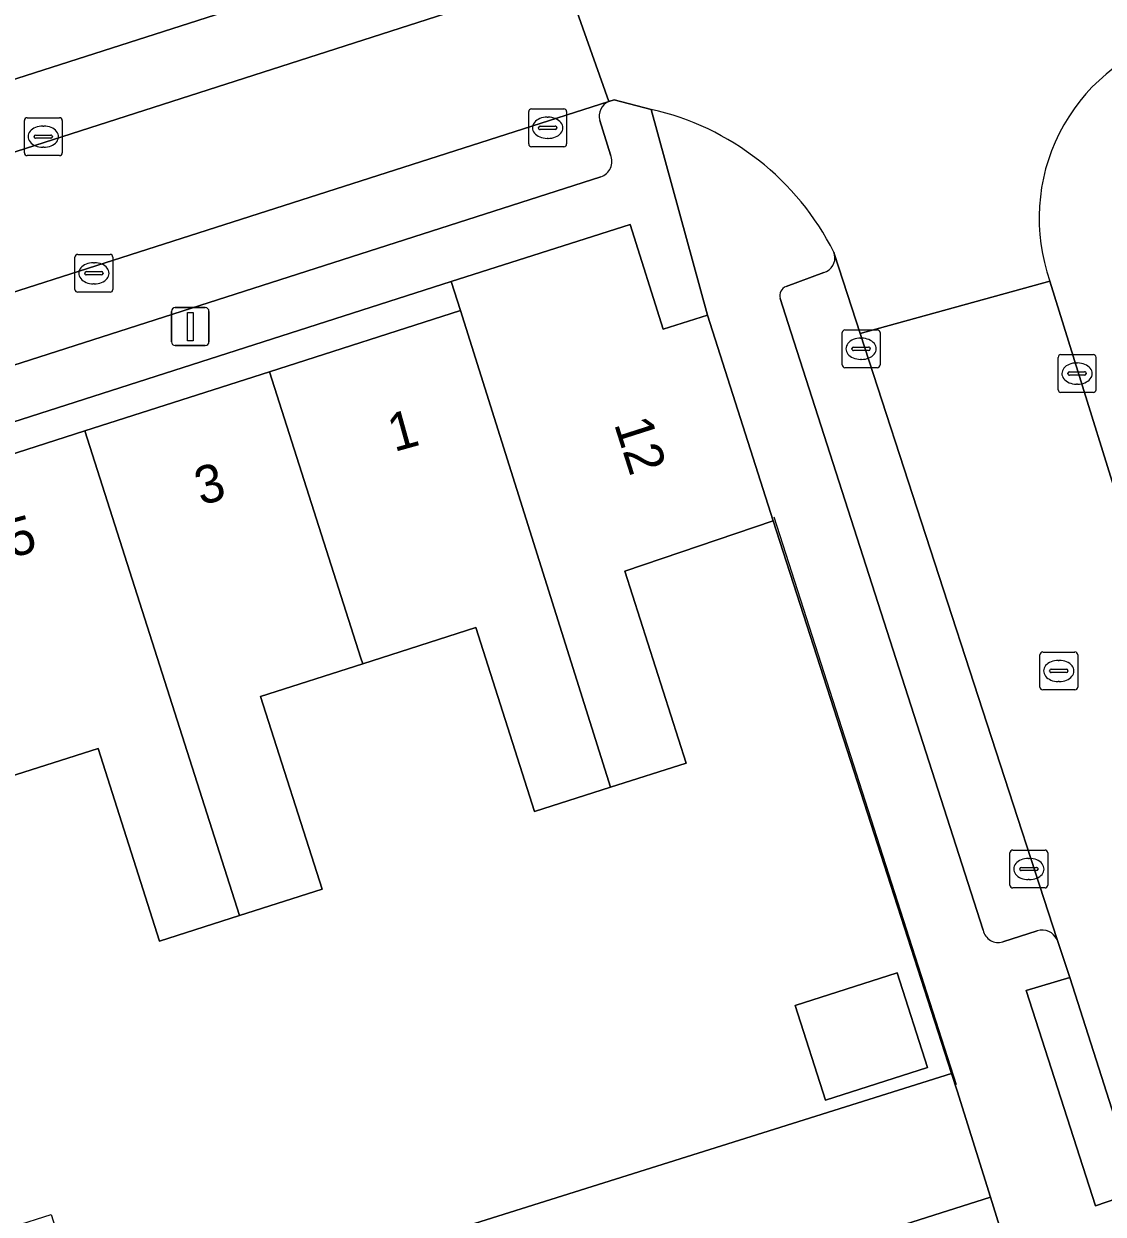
# Model space of a CAD drawing. Extents: x 159716 to 160783, y 383290 to 384031.
# Drawn here: x 160111.85 to 160140.37, y 383651.79 to 383683.23 of the extents above; entities that cross this region are included whole.
import ezdxf

# ---------------------------------------------------------------- set-up
doc = ezdxf.new("R2010")
doc.units = 0
for name, color, linetype in [('IMGEO_Erf', 7, 'Continuous'), ('IMGEO_Kolk', 7, 'Continuous'), ('IMGEO_Lichtmast', 7, 'Continuous'), ('IMGEO_Muur', 7, 'Continuous'), ('IMGEO_Pand', 7, 'Continuous'), ('IMGEO_Pand_nummerreeks', 7, 'Continuous'), ('IMGEO_Parkeervlak_open', 7, 'Continuous'), ('IMGEO_Rijbaan_lokaal_open', 7, 'Continuous'), ('IMGEO_Rioolput', 7, 'Continuous'), ('IMGEO_Voetpad_open', 7, 'Continuous')]:
    doc.layers.add(name, color=color, linetype=linetype)

msp = doc.modelspace()

# ---------------------------------------------------------------- linework, layer by layer
at = {"layer": 'IMGEO_Erf'}
for points in [[(160118.342, 383674.043), (160123.386, 383675.66), (160123.144, 383676.422), (160103.512, 383670.129), (160103.756, 383669.367), (160108.583, 383670.914), (160113.462, 383672.478)], [(160133.029, 383654.803), (160132.229, 383657.304), (160134.927, 383658.167), (160135.726, 383655.666)], [(160137.393, 383652.245), (160134.204, 383651.225), (160134.948, 383648.933), (160138.096, 383649.97)]]:
    msp.add_lwpolyline(points, close=True, dxfattribs=at)
msp.add_lwpolyline([(160109.579, 383650.836), (160112.572, 383651.783), (160113.511, 383648.814), (160115.357, 383649.398), (160115.5, 383648.947), (160136.361, 383655.511), (160131.65, 383670.104), (160127.73, 383668.779), (160129.351, 383663.706), (160127.35, 383663.067), (160125.347, 383662.428), (160123.796, 383667.287), (160120.805, 383666.331), (160118.108, 383665.469), (160119.734, 383660.377), (160117.551, 383659.679), (160115.439, 383659.005), (160113.814, 383664.092), (160111.044, 383663.207)], dxfattribs=at)
at = {"layer": 'IMGEO_Kolk'}
for p, q in [((160125.266, 383680.986), (160126.118, 383680.986)), ((160111.866, 383679.826), (160111.866, 383680.678)), ((160111.941, 383680.752), (160112.793, 383680.752)), ((160112.867, 383680.678), (160112.867, 383679.826)), ((160125.191, 383680.06), (160125.191, 383680.912)), ((160125.679, 383680.766), (160125.704, 383680.766)), ((160126.192, 383680.912), (160126.192, 383680.06)), ((160112.354, 383680.532), (160112.379, 383680.532)), ((160125.45, 383680.48), (160125.45, 383680.492)), ((160125.888, 383680.443), (160125.49, 383680.443)), ((160125.493, 383680.529), (160125.891, 383680.529)), ((160125.934, 383680.492), (160125.934, 383680.48)), ((160112.125, 383680.246), (160112.125, 383680.258)), ((160112.563, 383680.209), (160112.165, 383680.209)), ((160112.168, 383680.295), (160112.566, 383680.295)), ((160112.609, 383680.258), (160112.609, 383680.246)), ((160125.702, 383680.206), (160125.677, 383680.206)), ((160112.793, 383679.752), (160111.941, 383679.752)), ((160112.377, 383679.972), (160112.352, 383679.972)), ((160126.118, 383679.986), (160125.266, 383679.986)), ((160113.203, 383676.217), (160113.203, 383677.069)), ((160113.278, 383677.143), (160114.13, 383677.143)), ((160113.691, 383676.923), (160113.716, 383676.923)), ((160114.204, 383677.069), (160114.204, 383676.217)), ((160113.462, 383676.637), (160113.462, 383676.649)), ((160113.9, 383676.6), (160113.502, 383676.6)), ((160113.505, 383676.686), (160113.903, 383676.686)), ((160113.946, 383676.649), (160113.946, 383676.637)), ((160113.714, 383676.363), (160113.689, 383676.363)), ((160114.13, 383676.143), (160113.278, 383676.143)), ((160133.472, 383674.223), (160133.472, 383675.075)), ((160133.547, 383675.149), (160134.399, 383675.149)), ((160134.473, 383675.075), (160134.473, 383674.223)), ((160133.731, 383674.643), (160133.731, 383674.655)), ((160133.774, 383674.692), (160134.172, 383674.692)), ((160133.96, 383674.929), (160133.985, 383674.929)), ((160134.215, 383674.655), (160134.215, 383674.643)), ((160134.169, 383674.606), (160133.771, 383674.606)), ((160133.983, 383674.369), (160133.958, 383674.369)), ((160139.177, 383673.569), (160139.177, 383674.421)), ((160139.252, 383674.495), (160140.104, 383674.495)), ((160140.178, 383674.421), (160140.178, 383673.569)), ((160134.399, 383674.149), (160133.547, 383674.149)), ((160139.479, 383674.038), (160139.877, 383674.038)), ((160139.665, 383674.275), (160139.69, 383674.275)), ((160139.436, 383673.989), (160139.436, 383674.001)), ((160139.874, 383673.952), (160139.476, 383673.952)), ((160139.688, 383673.715), (160139.663, 383673.715)), ((160139.92, 383674.001), (160139.92, 383673.989)), ((160140.104, 383673.495), (160139.252, 383673.495)), ((160137.904, 383660.482), (160137.904, 383661.334)), ((160137.979, 383661.408), (160138.831, 383661.408)), ((160138.392, 383661.188), (160138.417, 383661.188)), ((160138.905, 383661.334), (160138.905, 383660.482)), ((160138.163, 383660.902), (160138.163, 383660.914)), ((160138.601, 383660.865), (160138.203, 383660.865)), ((160138.206, 383660.951), (160138.604, 383660.951)), ((160138.647, 383660.914), (160138.647, 383660.902)), ((160138.415, 383660.628), (160138.39, 383660.628)), ((160138.831, 383660.408), (160137.979, 383660.408))]:
    msp.add_line(p, q, dxfattribs=at)
for points in [[(160125.266, 383680.986), (160126.118, 383680.986)], [(160111.866, 383679.826), (160111.866, 383680.678)], [(160111.941, 383680.752), (160112.793, 383680.752)], [(160112.867, 383680.678), (160112.867, 383679.826)], [(160125.191, 383680.06), (160125.191, 383680.912)], [(160126.192, 383680.912), (160126.192, 383680.06)], [(160112.793, 383679.752), (160111.941, 383679.752)], [(160126.118, 383679.986), (160125.266, 383679.986)], [(160113.203, 383676.217), (160113.203, 383677.069)], [(160113.278, 383677.143), (160114.13, 383677.143)], [(160114.204, 383677.069), (160114.204, 383676.217)], [(160114.13, 383676.143), (160113.278, 383676.143)], [(160133.472, 383674.223), (160133.472, 383675.075)], [(160133.547, 383675.149), (160134.399, 383675.149)], [(160134.473, 383675.075), (160134.473, 383674.223)], [(160139.177, 383673.569), (160139.177, 383674.421)], [(160139.252, 383674.495), (160140.104, 383674.495)], [(160140.178, 383674.421), (160140.178, 383673.569)], [(160134.399, 383674.149), (160133.547, 383674.149)], [(160140.104, 383673.495), (160139.252, 383673.495)], [(160137.904, 383660.482), (160137.904, 383661.334)], [(160137.979, 383661.408), (160138.831, 383661.408)], [(160138.905, 383661.334), (160138.905, 383660.482)], [(160138.831, 383660.408), (160137.979, 383660.408)]]:
    msp.add_lwpolyline(points, dxfattribs=at)
for centre, radius, start, end in [((160125.268, 383680.91), 0.0765, 91.552, 178.448), ((160125.268, 383680.91), 0.0765, 91.552, 178.448), ((160126.116, 383680.91), 0.0765, 1.552, 88.448), ((160126.116, 383680.91), 0.0765, 1.552, 88.448), ((160111.943, 383680.676), 0.0765, 91.552, 178.448), ((160111.943, 383680.676), 0.0765, 91.552, 178.448), ((160112.791, 383680.676), 0.0765, 1.552, 88.448), ((160112.791, 383680.676), 0.0765, 1.552, 88.448), ((160125.49, 383680.489), 0.0403, 85.8775, 175.7526), ((160125.487, 383680.479), 0.0366, 178.938, 274.7102), ((160125.891, 383680.486), 0.043, 264.8664, 352.4533), ((160125.895, 383680.491), 0.0386, 1.7309, 96.639), ((160112.165, 383680.255), 0.0403, 85.8775, 175.7526), ((160112.162, 383680.245), 0.0366, 178.938, 274.7102), ((160112.566, 383680.252), 0.043, 264.8664, 352.4533), ((160112.57, 383680.257), 0.0386, 1.7309, 96.639), ((160125.268, 383680.062), 0.0765, 181.552, 268.448), ((160125.268, 383680.062), 0.0765, 181.552, 268.448), ((160126.116, 383680.062), 0.0765, 271.552, 358.448), ((160126.116, 383680.062), 0.0765, 271.552, 358.448), ((160111.943, 383679.828), 0.0765, 181.552, 268.448), ((160111.943, 383679.828), 0.0765, 181.552, 268.448), ((160112.791, 383679.828), 0.0765, 271.552, 358.448), ((160112.791, 383679.828), 0.0765, 271.552, 358.448), ((160113.28, 383677.067), 0.0765, 91.552, 178.448), ((160113.28, 383677.067), 0.0765, 91.552, 178.448), ((160114.128, 383677.067), 0.0765, 1.552, 88.448), ((160114.128, 383677.067), 0.0765, 1.552, 88.448), ((160113.502, 383676.646), 0.0403, 85.8775, 175.7526), ((160113.499, 383676.636), 0.0366, 178.938, 274.7102), ((160113.903, 383676.643), 0.043, 264.8664, 352.4533), ((160113.907, 383676.648), 0.0386, 1.7309, 96.639), ((160113.28, 383676.219), 0.0765, 181.552, 268.448), ((160113.28, 383676.219), 0.0765, 181.552, 268.448), ((160114.128, 383676.219), 0.0765, 271.552, 358.448), ((160114.128, 383676.219), 0.0765, 271.552, 358.448), ((160133.549, 383675.073), 0.0765, 91.552, 178.448), ((160133.549, 383675.073), 0.0765, 91.552, 178.448), ((160134.397, 383675.073), 0.0765, 1.552, 88.448), ((160134.397, 383675.073), 0.0765, 1.552, 88.448), ((160133.771, 383674.652), 0.0403, 85.8775, 175.7526), ((160134.176, 383674.654), 0.0386, 1.7309, 96.639), ((160133.768, 383674.642), 0.0366, 178.938, 274.7102), ((160134.172, 383674.649), 0.043, 264.8664, 352.4533), ((160139.254, 383674.419), 0.0765, 91.552, 178.448), ((160139.254, 383674.419), 0.0765, 91.552, 178.448), ((160140.102, 383674.419), 0.0765, 1.552, 88.448), ((160140.102, 383674.419), 0.0765, 1.552, 88.448), ((160133.549, 383674.225), 0.0765, 181.552, 268.448), ((160133.549, 383674.225), 0.0765, 181.552, 268.448), ((160134.397, 383674.225), 0.0765, 271.552, 358.448), ((160134.397, 383674.225), 0.0765, 271.552, 358.448), ((160139.476, 383673.998), 0.0403, 85.8775, 175.7526), ((160139.881, 383674), 0.0386, 1.7309, 96.639), ((160139.473, 383673.988), 0.0366, 178.938, 274.7102), ((160139.877, 383673.995), 0.043, 264.8664, 352.4533), ((160139.254, 383673.571), 0.0765, 181.552, 268.448), ((160139.254, 383673.571), 0.0765, 181.552, 268.448), ((160140.102, 383673.571), 0.0765, 271.552, 358.448), ((160140.102, 383673.571), 0.0765, 271.552, 358.448), ((160137.981, 383661.332), 0.0765, 91.552, 178.448), ((160137.981, 383661.332), 0.0765, 91.552, 178.448), ((160138.829, 383661.332), 0.0765, 1.552, 88.448), ((160138.829, 383661.332), 0.0765, 1.552, 88.448), ((160138.203, 383660.911), 0.0403, 85.8775, 175.7526), ((160138.2, 383660.901), 0.0366, 178.938, 274.7102), ((160138.604, 383660.908), 0.043, 264.8664, 352.4533), ((160138.608, 383660.913), 0.0386, 1.7309, 96.639), ((160137.981, 383660.484), 0.0765, 181.552, 268.448), ((160137.981, 383660.484), 0.0765, 181.552, 268.448), ((160138.829, 383660.484), 0.0765, 271.552, 358.448), ((160138.829, 383660.484), 0.0765, 271.552, 358.448)]:
    msp.add_arc(centre, radius, start, end, dxfattribs=at)
for centre, major_axis, ratio, start_param, end_param in [((160125.678, 383680.486), (-0.387, 0.002), 0.722429, 4.712389, 7.853982), ((160125.703, 383680.486), (-0.39, 0.002), 0.717154, 1.570796, 4.712389), ((160112.353, 383680.252), (-0.387, 0.002), 0.722429, 4.712389, 7.853982), ((160112.378, 383680.252), (-0.39, 0.002), 0.717154, 1.570796, 4.712389), ((160113.69, 383676.643), (-0.387, 0.002), 0.722429, 4.712389, 7.853982), ((160113.715, 383676.643), (-0.39, 0.002), 0.717154, 1.570796, 4.712389), ((160133.959, 383674.649), (-0.387, 0.002), 0.722429, 4.712389, 7.853982), ((160133.984, 383674.649), (-0.39, 0.002), 0.717154, 1.570796, 4.712389), ((160139.664, 383673.995), (-0.387, 0.002), 0.722429, 4.712389, 7.853982), ((160139.689, 383673.995), (-0.39, 0.002), 0.717154, 1.570796, 4.712389), ((160138.391, 383660.908), (-0.387, 0.002), 0.722429, 4.712389, 7.853982), ((160138.416, 383660.908), (-0.39, 0.002), 0.717154, 1.570796, 4.712389)]:
    msp.add_ellipse(centre, major_axis=major_axis, ratio=ratio, start_param=start_param, end_param=end_param, dxfattribs=at)
at = {"layer": 'IMGEO_Lichtmast'}
for p, q in [((160115.754, 383674.836), (160115.754, 383675.636)), ((160115.754, 383675.636), (160115.754, 383674.836)), ((160115.854, 383675.736), (160116.644, 383675.736)), ((160116.644, 383675.736), (160115.854, 383675.736)), ((160116.744, 383675.636), (160116.744, 383674.836)), ((160116.744, 383674.836), (160116.744, 383675.636)), ((160116.644, 383674.736), (160115.854, 383674.736)), ((160115.854, 383674.736), (160116.644, 383674.736))]:
    msp.add_line(p, q, dxfattribs=at)
msp.add_lwpolyline([(160116.174, 383675.611), (160116.324, 383675.611), (160116.324, 383674.861), (160116.174, 383674.861), (160116.174, 383675.611)], dxfattribs=at)
for centre, start, end in [((160115.854, 383675.636), 90, 180), ((160115.854, 383675.636), 90, 180), ((160116.644, 383675.636), 0, 90), ((160116.644, 383675.636), 360, 90), ((160115.854, 383674.836), 180, 270), ((160115.854, 383674.836), 180, 270), ((160116.644, 383674.836), 270, 0), ((160116.644, 383674.836), 270, 0)]:
    msp.add_arc(centre, 0.1, start, end, dxfattribs=at)
at = {"layer": 'IMGEO_Muur'}
msp.add_lwpolyline([(160131.667, 383670.211), (160136.481, 383655.215)], dxfattribs=at)
at = {"layer": 'IMGEO_Pand'}
for points in [[(160129.915, 383675.538), (160128.746, 383675.167), (160127.87, 383677.928), (160123.144, 383676.422), (160123.386, 383675.66), (160127.35, 383663.067), (160129.351, 383663.706), (160127.73, 383668.779), (160131.65, 383670.104)], [(160123.386, 383675.66), (160118.342, 383674.043), (160120.758, 383666.478), (160120.805, 383666.331), (160123.796, 383667.287), (160125.347, 383662.428), (160127.35, 383663.067)], [(160118.342, 383674.043), (160113.462, 383672.478), (160117.551, 383659.679), (160119.734, 383660.377), (160118.108, 383665.469), (160120.805, 383666.331), (160120.758, 383666.478)], [(160113.462, 383672.478), (160108.583, 383670.914), (160111.044, 383663.207), (160113.814, 383664.092), (160115.439, 383659.005), (160117.551, 383659.679)], [(160133.029, 383654.803), (160135.726, 383655.666), (160134.927, 383658.167), (160132.229, 383657.304)]]:
    msp.add_lwpolyline(points, close=True, dxfattribs=at)
at = {"layer": 'IMGEO_Parkeervlak_open'}
for points in [[(160124.861, 383686.019), (160096.9, 383677.061)], [(160096.699, 383675.06), (160126.127, 383684.515)], [(160127.305, 383681.179), (160097.72, 383671.705)], [(160127.352, 383679.772), (160127.071, 383680.679)], [(160099.065, 383670.2), (160127.096, 383679.187)], [(160133.948, 383675.056), (160133.272, 383677.136)], [(160132.988, 383676.665), (160131.993, 383676.295)], [(160131.833, 383675.978), (160132.115, 383675.101), (160137.195, 383659.29)], [(160139.151, 383659.043), (160133.948, 383675.056)], [(160137.717, 383658.983), (160138.626, 383659.275)]]:
    msp.add_lwpolyline(points, dxfattribs=at)
for centre, radius, start, end in [((160127.469, 383680.798), 0.415, 113.2237, 196.6171), ((160126.951, 383679.599), 0.437, 289.4349, 23.2961), ((160132.875, 383677.054), 0.406, 286.2164, 11.6059), ((160132.087, 383676.049), 0.264, 110.9387, 195.4982), ((160137.601, 383659.383), 0.417, 192.9303, 286.1482), ((160138.753, 383658.852), 0.442, 25.65, 106.6683)]:
    msp.add_arc(centre, radius, start, end, dxfattribs=at)
at = {"layer": 'IMGEO_Rijbaan_lokaal_open'}
for points in [[(160140.365, 383689.087), (160131.741, 383686.293), (160127.013, 383684.761), (160126.463, 383684.611), (160126.127, 383684.515), (160127.305, 383681.179), (160127.453, 383681.227), (160128.426, 383680.973)], [(160097.72, 383671.705), (160127.305, 383681.179), (160126.127, 383684.515), (160096.699, 383675.06), (160080.374, 383669.741)], [(160133.252, 383677.2), (160133.272, 383677.136), (160133.948, 383675.056), (160138.962, 383676.438)], [(160138.962, 383676.438), (160141.47, 383668.37)]]:
    msp.add_lwpolyline(points, dxfattribs=at)
msp.add_lwpolyline([(160141.47, 383668.37), (160138.962, 383676.438), (160133.948, 383675.056), (160139.151, 383659.043), (160139.483, 383658.043), (160141.29, 383652.4), (160141.576, 383651.473), (160148.415, 383629.989), (160151.141, 383621.545), (160156.009, 383623.174)], close=True, dxfattribs=at)
for centre, radius, start, end in [((160143.65, 383678.101), 4.974, 106.9878, 199.5257), ((160143.65, 383678.101), 4.974, 106.9878, 199.5257), ((160126.86, 383673.997), 7.15, 26.6164, 77.3465)]:
    msp.add_arc(centre, radius, start, end, dxfattribs=at)
at = {"layer": 'IMGEO_Rioolput'}
for p, q in [((160138.695, 383665.714), (160138.695, 383666.566)), ((160138.77, 383666.64), (160139.622, 383666.64)), ((160139.696, 383666.566), (160139.696, 383665.714)), ((160138.997, 383666.183), (160139.395, 383666.183)), ((160139.183, 383666.42), (160139.208, 383666.42)), ((160138.954, 383666.134), (160138.954, 383666.146)), ((160139.392, 383666.097), (160138.994, 383666.097)), ((160139.206, 383665.86), (160139.181, 383665.86)), ((160139.438, 383666.146), (160139.438, 383666.134)), ((160139.622, 383665.64), (160138.77, 383665.64))]:
    msp.add_line(p, q, dxfattribs=at)
for points in [[(160138.695, 383665.714), (160138.695, 383666.566)], [(160138.77, 383666.64), (160139.622, 383666.64)], [(160139.696, 383666.566), (160139.696, 383665.714)], [(160139.622, 383665.64), (160138.77, 383665.64)]]:
    msp.add_lwpolyline(points, dxfattribs=at)
for centre, radius, start, end in [((160138.772, 383666.564), 0.0765, 91.552, 178.448), ((160138.772, 383666.564), 0.0765, 91.552, 178.448), ((160139.62, 383666.564), 0.0765, 1.552, 88.448), ((160139.62, 383666.564), 0.0765, 1.552, 88.448), ((160138.994, 383666.143), 0.0403, 85.8775, 175.7526), ((160139.399, 383666.145), 0.0386, 1.7309, 96.639), ((160138.991, 383666.133), 0.0366, 178.938, 274.7102), ((160139.395, 383666.14), 0.043, 264.8664, 352.4533), ((160138.772, 383665.716), 0.0765, 181.552, 268.448), ((160138.772, 383665.716), 0.0765, 181.552, 268.448), ((160139.62, 383665.716), 0.0765, 271.552, 358.448), ((160139.62, 383665.716), 0.0765, 271.552, 358.448)]:
    msp.add_arc(centre, radius, start, end, dxfattribs=at)
for centre, major_axis, ratio, start_param, end_param in [((160139.182, 383666.14), (-0.387, 0.002), 0.722429, 4.712389, 7.853982), ((160139.207, 383666.14), (-0.39, 0.002), 0.717154, 1.570796, 4.712389)]:
    msp.add_ellipse(centre, major_axis=major_axis, ratio=ratio, start_param=start_param, end_param=end_param, dxfattribs=at)
at = {"layer": 'IMGEO_Voetpad_open'}
for points in [[(160096.9, 383677.061), (160124.861, 383686.019)], [(160123.144, 383676.422), (160127.87, 383677.928), (160128.746, 383675.167), (160129.915, 383675.538), (160128.426, 383680.973), (160127.453, 383681.227), (160127.305, 383681.179)], [(160128.426, 383680.973), (160129.915, 383675.538), (160131.65, 383670.104), (160136.361, 383655.511), (160136.509, 383655.053), (160137.393, 383652.245), (160138.096, 383649.97), (160139.479, 383645.604), (160155.168, 383596.67), (160156.559, 383592.314), (160157.321, 383590.056), (160158.044, 383583.381)], [(160127.071, 383680.679), (160127.352, 383679.772)], [(160127.096, 383679.187), (160099.065, 383670.2)], [(160133.272, 383677.136), (160133.252, 383677.2)], [(160131.993, 383676.295), (160132.988, 383676.665)], [(160078.849, 383664.464), (160080.722, 383656.898), (160083.877, 383657.906), (160083.187, 383660.108), (160088.233, 383661.733), (160096.493, 383664.423), (160097.864, 383664.862), (160100.065, 383665.565), (160099.062, 383668.708), (160103.381, 383670.087), (160103.512, 383670.129), (160123.144, 383676.422)], [(160137.195, 383659.29), (160132.115, 383675.101), (160131.833, 383675.978)], [(160138.626, 383659.275), (160137.717, 383658.983)], [(160138.333, 383657.7), (160139.483, 383658.043), (160139.151, 383659.043)], [(160141.576, 383651.473), (160141.29, 383652.4), (160140.166, 383652.01), (160138.333, 383657.7)], [(160110.764, 383596.41), (160127.456, 383601.679), (160120.476, 383623.696), (160119.09, 383628.068), (160113.81, 383644.725), (160123.842, 383647.93), (160129.46, 383649.725), (160134.204, 383651.225), (160137.393, 383652.245), (160136.509, 383655.053), (160136.361, 383655.511), (160115.5, 383648.947), (160115.357, 383649.398), (160113.511, 383648.814), (160113.539, 383648.726), (160110.546, 383647.779)]]:
    msp.add_lwpolyline(points, dxfattribs=at)
msp.add_lwpolyline([(160139.483, 383658.043), (160138.333, 383657.7), (160140.166, 383652.01), (160141.29, 383652.4)], close=True, dxfattribs=at)
for centre, radius, start, end in [((160127.469, 383680.798), 0.415, 113.2237, 196.6171), ((160126.86, 383673.997), 7.15, 26.6164, 77.3465), ((160126.951, 383679.599), 0.437, 289.4349, 23.2961), ((160132.875, 383677.054), 0.406, 286.2164, 11.6059), ((160132.087, 383676.049), 0.264, 110.9387, 195.4982), ((160137.601, 383659.383), 0.417, 192.9303, 286.1482), ((160138.753, 383658.852), 0.442, 25.65, 106.6683)]:
    msp.add_arc(centre, radius, start, end, dxfattribs=at)

# ---------------------------------------------------------------- texts
at = {"layer": 'IMGEO_Pand_nummerreeks'}
for s, rotation, p in [('1', 15.4985, (160121.636, 383671.92)), ('12', 287.7271, (160127.439, 383672.668)), ('3', 15.4985, (160116.531, 383670.506)), ('5', 15.4985, (160111.537, 383669.121))]:
    msp.add_text(s, height=1, rotation=rotation, dxfattribs=at).set_placement(p)

doc.saveas('drawing.dxf')
